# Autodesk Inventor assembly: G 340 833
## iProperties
Created: 2006-10
Part Number: G 340 833
Document SubType Name: Schweißkonstruktion
Designer: I.Baliuc
Manufacturer: Standard
Standards Organization: Custom
Description: Funkenhorn, fest (kpl.)
Material: gelötet
Mass: 927.864 g
Surface Area: 266.678 cm^2
Volume: 103.723 cm^3
Density: 8.94562 g/cm^3
Title: Funkenhorn fest, kompl.
Company: Mayer & Müller AG Schaltgeräte
Author: T.Messerschmitt
Revision Number: 340833
